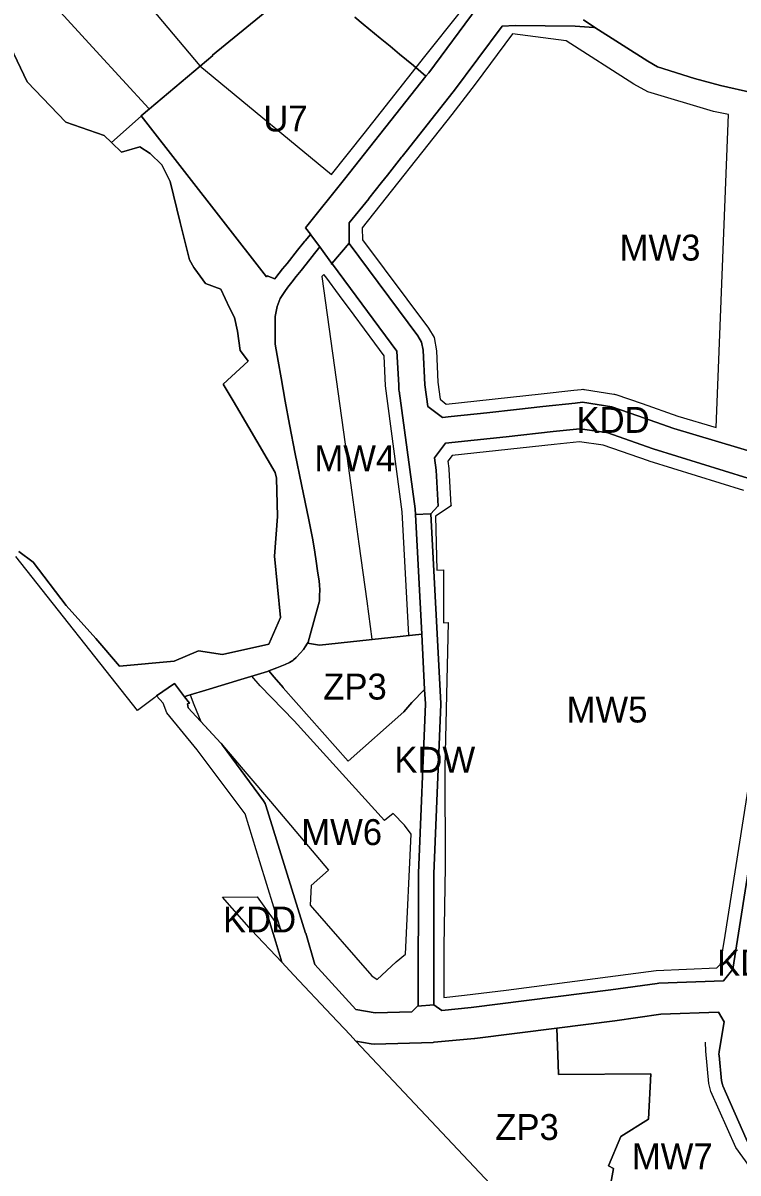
# Model space of a CAD drawing. Extents: x 7425930 to 7427318, y 5544765 to 5546387.
# Drawn here: x 7426422.5 to 7426698.5, y 5545008.8 to 5545452.3 of the extents above; entities that cross this region are included whole.
import ezdxf

# ---------------------------------------------------------------- set-up
doc = ezdxf.new("R2010")
doc.units = 0
for name, color, linetype in [('linie_rozgraniczajace', 7, 'Continuous'), ('linie_zabudowy_nieprzekraczalne', 7, 'Continuous'), ('linie_zabudowy_obowiazujace', 7, 'Continuous'), ('oznaczenia_przeznaczen', 7, 'Continuous')]:
    doc.layers.add(name, color=color, linetype=linetype)

msp = doc.modelspace()

# ---------------------------------------------------------------- linework, layer by layer
at = {"layer": 'linie_rozgraniczajace'}
for points in [[(7426531.91, 5545469.68), (7426495.6, 5545439.93), (7426495.7, 5545439.81), (7426471.26, 5545419.17), (7426471.04, 5545419.4), (7426450.76, 5545441.52), (7426428.57, 5545465.75)], [(7426550.61, 5545454.54), (7426553.81, 5545451.91), (7426560.37, 5545446.51), (7426564.14, 5545443.41), (7426567.86, 5545440.35), (7426573.15, 5545435.88), (7426576.02, 5545433.47), (7426578.02, 5545431.79), (7426546.56, 5545392.08), (7426531.53, 5545373.36), (7426533.4, 5545370.84), (7426533.41, 5545370.82), (7426531.38, 5545368.35), (7426531.11, 5545368.02), (7426528.49, 5545364.77), (7426524.39, 5545359.61), (7426522.68, 5545357.53), (7426520.11, 5545354.23), (7426519.67, 5545353.61), (7426516.75, 5545354.84), (7426516.51, 5545354.48), (7426468.15, 5545416.47), (7426468.12, 5545416.51), (7426471.26, 5545419.17), (7426495.7, 5545439.81), (7426495.6, 5545439.93), (7426531.91, 5545469.68)], [(7426428.57, 5545465.75), (7426450.76, 5545441.52), (7426471.04, 5545419.4), (7426471.26, 5545419.17), (7426468.12, 5545416.51), (7426468.15, 5545416.47), (7426468.08, 5545416.46), (7426456.63, 5545406.26), (7426453.83, 5545408.94), (7426439.06, 5545414.08), (7426424.06, 5545429.61), (7426417.71, 5545443.09), (7426415.29, 5545454.53)], [(7426638.81, 5545453.6), (7426643.25, 5545450.62), (7426642.75, 5545450.65), (7426635.57, 5545451.11), (7426612.46, 5545451.38), (7426607.43, 5545451.14), (7426588.68, 5545425.93), (7426588.59, 5545425.82), (7426588.57, 5545425.79), (7426570.37, 5545402.81), (7426568.81, 5545400.84), (7426568.64, 5545400.63), (7426568.64, 5545400.65), (7426563.18, 5545393.71), (7426563.18, 5545393.73), (7426563.14, 5545393.69), (7426560.9, 5545390.86), (7426555.95, 5545384.61), (7426555.94, 5545384.6), (7426555.93, 5545384.58), (7426548.43, 5545375.24), (7426548.35, 5545367.45), (7426541.73, 5545359.6), (7426539, 5545363.28), (7426537.02, 5545365.95), (7426533.41, 5545370.82), (7426533.4, 5545370.84), (7426531.53, 5545373.36), (7426546.56, 5545392.08), (7426578.02, 5545431.79), (7426579.11, 5545433.17), (7426597.8, 5545458.3)], [(7426597.8, 5545458.3), (7426579.11, 5545433.17), (7426578.02, 5545431.79), (7426576.02, 5545433.47), (7426573.15, 5545435.88), (7426567.86, 5545440.35), (7426564.14, 5545443.41), (7426560.37, 5545446.51), (7426553.81, 5545451.91), (7426550.61, 5545454.54)], [(7426704.2, 5545425.45), (7426691.68, 5545428.29), (7426681.66, 5545430.95), (7426667.42, 5545435.49), (7426663.59, 5545437.66), (7426643.25, 5545450.62), (7426638.81, 5545453.6)], [(7426706.86, 5545286), (7426673.73, 5545295.93), (7426659.83, 5545300.81), (7426649.7, 5545304.3), (7426638.44, 5545306.06), (7426635.65, 5545305.77), (7426623.07, 5545304.4), (7426612.94, 5545303.29), (7426601.56, 5545302.04), (7426587.78, 5545300.54), (7426584.4, 5545300.17), (7426578.71, 5545304.48), (7426577.62, 5545312.79), (7426576.94, 5545326.13), (7426576.28, 5545329.28), (7426574.86, 5545331.74), (7426548.35, 5545367.35), (7426548.35, 5545367.45), (7426548.43, 5545375.24), (7426555.93, 5545384.58), (7426555.94, 5545384.6), (7426555.95, 5545384.61), (7426560.9, 5545390.86), (7426563.14, 5545393.69), (7426563.18, 5545393.73), (7426563.18, 5545393.71), (7426568.64, 5545400.65), (7426568.64, 5545400.63), (7426568.81, 5545400.84), (7426570.37, 5545402.81), (7426588.57, 5545425.79), (7426588.59, 5545425.82), (7426588.68, 5545425.93), (7426607.43, 5545451.14), (7426612.46, 5545451.38), (7426635.57, 5545451.11), (7426642.75, 5545450.65), (7426643.25, 5545450.62), (7426663.59, 5545437.66), (7426667.42, 5545435.49), (7426681.66, 5545430.95), (7426691.68, 5545428.29), (7426704.2, 5545425.45)], [(7426417.71, 5545443.09), (7426424.06, 5545429.61), (7426439.06, 5545414.08), (7426453.83, 5545408.94), (7426456.63, 5545406.26), (7426456.79, 5545406.11), (7426460.52, 5545402.53), (7426467.63, 5545404.58), (7426471.52, 5545401.96), (7426476.11, 5545397.61), (7426479.27, 5545391.18), (7426483.12, 5545375.39), (7426486.73, 5545361.04), (7426488.37, 5545358.08), (7426488.76, 5545357.54), (7426492.91, 5545351.83), (7426498.79, 5545349.67), (7426502.24, 5545342.5), (7426504.15, 5545338.8), (7426505.25, 5545333.42), (7426506.31, 5545326.02), (7426507.94, 5545323.89), (7426509.38, 5545321.86), (7426499.78, 5545313.02), (7426503.55, 5545306.64), (7426509.66, 5545296.31), (7426519.88, 5545278.94), (7426520.33, 5545276.73), (7426520.7, 5545261.99)], [(7426479.27, 5545391.18), (7426476.11, 5545397.61), (7426471.52, 5545401.96), (7426467.63, 5545404.58), (7426460.52, 5545402.53), (7426456.79, 5545406.11), (7426456.63, 5545406.26), (7426468.08, 5545416.46), (7426468.15, 5545416.47), (7426516.51, 5545354.48), (7426516.75, 5545354.84), (7426519.67, 5545353.61), (7426520.11, 5545354.23), (7426522.68, 5545357.53), (7426524.39, 5545359.61), (7426528.49, 5545364.77), (7426531.11, 5545368.02), (7426531.38, 5545368.35), (7426533.41, 5545370.82), (7426537.02, 5545365.95), (7426535.05, 5545363.42), (7426533.24, 5545361.1), (7426529.88, 5545356.84), (7426527.98, 5545354.52), (7426526.25, 5545352.4), (7426524.76, 5545350.44), (7426523.6, 5545348.78), (7426522.55, 5545347.3), (7426521.76, 5545346.13), (7426520.63, 5545343.03), (7426519.82, 5545339.09), (7426519.81, 5545334.06), (7426519.88, 5545328.45), (7426521.02, 5545321.87), (7426522.12, 5545315.47), (7426523.66, 5545306.53), (7426525.34, 5545297.48), (7426527.58, 5545286.21), (7426530, 5545274.35), (7426532.79, 5545260.69), (7426534.19, 5545253.64), (7426534.92, 5545249.86), (7426535.54, 5545245.63), (7426536.33, 5545240.18), (7426536.76, 5545237.25), (7426536.93, 5545235.52), (7426537.08, 5545233.68), (7426536.97, 5545231.36), (7426536.91, 5545229.43), (7426536.83, 5545228.94), (7426536.22, 5545226.68), (7426533.74, 5545217.72), (7426532.93, 5545214.93), (7426532.52, 5545213.56), (7426532.26, 5545213.13), (7426531.43, 5545211.72), (7426530.71, 5545210.74), (7426529.61, 5545209.41), (7426527.88, 5545207.68), (7426526.93, 5545206.77), (7426526.62, 5545206.5), (7426525.38, 5545205.72), (7426523.63, 5545204.98), (7426520.4, 5545203.65), (7426517.33, 5545202.45), (7426516.86, 5545202.27), (7426506.56, 5545199.12), (7426494.29, 5545195.39), (7426485.75, 5545192.8), (7426484.76, 5545192.48), (7426480.9, 5545197.54), (7426474.06, 5545192.78), (7426473.36, 5545192.25), (7426466.72, 5545187.23), (7426419.78, 5545246.57)], [(7426420.88, 5545248.48), (7426426.47, 5545244.42), (7426439.13, 5545227.66), (7426450.61, 5545214.89), (7426459.74, 5545204.29), (7426480.85, 5545206.15), (7426490.27, 5545210.19), (7426499.47, 5545208.74), (7426517.34, 5545212.74), (7426521.84, 5545223.01), (7426519.61, 5545246.75), (7426520.7, 5545261.99), (7426520.33, 5545276.73), (7426519.88, 5545278.94), (7426509.66, 5545296.31), (7426503.55, 5545306.64), (7426499.78, 5545313.02), (7426509.38, 5545321.86), (7426507.94, 5545323.89), (7426506.31, 5545326.02), (7426505.25, 5545333.42), (7426504.15, 5545338.8), (7426502.24, 5545342.5), (7426498.79, 5545349.67), (7426492.91, 5545351.83), (7426488.76, 5545357.54), (7426488.37, 5545358.08), (7426486.73, 5545361.04), (7426483.12, 5545375.39), (7426479.27, 5545391.18)], [(7426702.26, 5545276.73), (7426665.69, 5545288.13), (7426647.84, 5545294.37), (7426647.67, 5545294.43), (7426637.42, 5545295.85), (7426627.12, 5545294.78), (7426608.93, 5545292.79), (7426596.61, 5545291.44), (7426585.6, 5545290.24), (7426581.33, 5545284.68), (7426581.96, 5545279.87), (7426582.79, 5545266.05), (7426582.58, 5545266.05), (7426579.96, 5545263.01), (7426579.83, 5545263.03), (7426573.94, 5545262.79), (7426573.83, 5545265.01), (7426567.62, 5545310.45), (7426567.6, 5545310.68), (7426567.6, 5545310.69), (7426567.5, 5545312.59), (7426566.8, 5545325.78), (7426541.92, 5545359.34), (7426541.58, 5545359.36), (7426541.62, 5545359.46), (7426541.73, 5545359.6), (7426548.35, 5545367.45), (7426548.35, 5545367.35), (7426574.86, 5545331.74), (7426576.28, 5545329.28), (7426576.94, 5545326.13), (7426577.62, 5545312.79), (7426578.71, 5545304.48), (7426584.4, 5545300.17), (7426587.78, 5545300.54), (7426601.56, 5545302.04), (7426612.94, 5545303.29), (7426623.07, 5545304.4), (7426635.65, 5545305.77), (7426638.44, 5545306.06), (7426649.7, 5545304.3), (7426659.83, 5545300.81), (7426673.73, 5545295.93), (7426706.86, 5545286)], [(7426709.77, 5545171.52), (7426696.47, 5545087.37), (7426692.88, 5545082.9), (7426667.9, 5545082), (7426667.89, 5545081.99), (7426667.88, 5545082), (7426667.29, 5545081.94), (7426649.36, 5545079.43), (7426595.49, 5545072.62), (7426584.11, 5545071.53), (7426581.12, 5545073.63), (7426581.04, 5545073.68), (7426581, 5545076.17), (7426581.1, 5545124.22), (7426583.8, 5545189.61), (7426583.8, 5545189.85), (7426583.8, 5545189.87), (7426583.8, 5545189.89), (7426579.94, 5545262.99), (7426579.96, 5545263.01), (7426582.58, 5545266.05), (7426582.79, 5545266.05), (7426581.96, 5545279.87), (7426581.33, 5545284.68), (7426585.6, 5545290.24), (7426596.61, 5545291.44), (7426608.93, 5545292.79), (7426627.12, 5545294.78), (7426637.42, 5545295.85), (7426647.67, 5545294.43), (7426647.84, 5545294.37), (7426665.69, 5545288.13), (7426702.26, 5545276.73)], [(7426520.7, 5545261.99), (7426519.61, 5545246.75), (7426521.84, 5545223.01), (7426517.34, 5545212.74), (7426499.47, 5545208.74), (7426490.27, 5545210.19), (7426480.85, 5545206.15), (7426459.74, 5545204.29), (7426450.61, 5545214.89), (7426439.13, 5545227.66), (7426426.47, 5545244.42), (7426420.88, 5545248.48)], [(7426474.06, 5545192.78), (7426480.9, 5545197.54), (7426484.76, 5545192.48), (7426486.7, 5545189.95), (7426485.94, 5545189.72), (7426486.2, 5545188.19), (7426498.81, 5545174.63), (7426499.09, 5545174.33), (7426499.2, 5545174.17), (7426499.53, 5545173.81), (7426515.36, 5545152.34), (7426515.98, 5545151.3), (7426516.26, 5545150.56), (7426531.56, 5545101.33), (7426531.57, 5545101.3), (7426531.59, 5545101.24), (7426535.12, 5545089.17), (7426550.97, 5545071.89), (7426558.37, 5545070.53), (7426572.56, 5545070.94), (7426574.73, 5545073.12), (7426581.12, 5545073.63), (7426584.11, 5545071.53), (7426595.49, 5545072.62), (7426649.36, 5545079.43), (7426667.29, 5545081.94), (7426667.88, 5545082), (7426667.89, 5545081.99), (7426667.9, 5545082), (7426692.88, 5545082.9), (7426696.47, 5545087.37), (7426709.77, 5545171.52)], [(7426692.06, 5545044.32), (7426691.13, 5545054.08), (7426691.15, 5545054.23), (7426691.11, 5545054.4), (7426691.19, 5545055.65), (7426693.14, 5545067.12), (7426690.97, 5545070.83), (7426668.65, 5545070.02), (7426650.98, 5545067.54), (7426650.92, 5545067.54), (7426650.9, 5545067.53), (7426628.57, 5545064.71), (7426596.9, 5545060.71), (7426596.75, 5545060.69), (7426596.72, 5545060.69), (7426581.23, 5545059.2), (7426581.04, 5545059.22), (7426580.83, 5545059.17), (7426558.08, 5545058.51), (7426558, 5545058.53), (7426556.82, 5545058.61), (7426550.99, 5545059.69), (7426548.79, 5545062.03), (7426541.58, 5545069.68), (7426527.02, 5545085.15), (7426522.35, 5545090.1), (7426520.09, 5545097.82), (7426516.07, 5545110.75), (7426521.96, 5545102.53), (7426513.88, 5545128.83), (7426508.23, 5545147.27), (7426489.66, 5545172.05), (7426478.02, 5545186.31), (7426476.64, 5545189.98), (7426474.06, 5545192.78)], [(7426647.24, 5544992.98), (7426650.37, 5545010.58), (7426648.48, 5545011.56), (7426653.18, 5545022.87), (7426663.9, 5545029.53), (7426664.78, 5545047.04), (7426629.17, 5545046.79), (7426629.01, 5545050.75), (7426628.57, 5545064.71), (7426650.9, 5545067.53), (7426650.92, 5545067.54), (7426650.98, 5545067.54), (7426668.65, 5545070.02), (7426690.97, 5545070.83), (7426693.14, 5545067.12), (7426691.19, 5545055.65), (7426691.11, 5545054.4), (7426691.15, 5545054.23), (7426691.13, 5545054.08), (7426692.06, 5545044.32), (7426692.43, 5545042.95), (7426692.54, 5545042.47), (7426701.58, 5545021.92)], [(7426715.65, 5545001.38), (7426702.14, 5545020.92), (7426701.63, 5545021.81), (7426701.61, 5545021.87), (7426701.58, 5545021.92), (7426692.54, 5545042.47), (7426692.43, 5545042.95), (7426692.06, 5545044.32)]]:
    msp.add_lwpolyline(points, dxfattribs=at)
for points in [[(7426519.88, 5545328.45), (7426519.81, 5545334.06), (7426519.82, 5545339.09), (7426520.63, 5545343.03), (7426521.76, 5545346.13), (7426522.55, 5545347.3), (7426523.6, 5545348.78), (7426524.76, 5545350.44), (7426526.25, 5545352.4), (7426527.98, 5545354.52), (7426529.88, 5545356.84), (7426533.24, 5545361.1), (7426535.05, 5545363.42), (7426537.02, 5545365.95), (7426539, 5545363.28), (7426541.73, 5545359.6), (7426541.62, 5545359.46), (7426541.58, 5545359.36), (7426541.92, 5545359.34), (7426566.8, 5545325.78), (7426567.5, 5545312.59), (7426567.6, 5545310.69), (7426567.6, 5545310.68), (7426567.62, 5545310.45), (7426573.83, 5545265.01), (7426573.94, 5545262.79), (7426576.39, 5545216.57), (7426536.9, 5545212.38), (7426535.39, 5545212.62), (7426532.26, 5545213.13), (7426532.52, 5545213.56), (7426532.93, 5545214.93), (7426533.74, 5545217.72), (7426536.22, 5545226.68), (7426536.83, 5545228.94), (7426536.91, 5545229.43), (7426536.97, 5545231.36), (7426537.08, 5545233.68), (7426536.93, 5545235.52), (7426536.76, 5545237.25), (7426536.33, 5545240.18), (7426535.54, 5545245.63), (7426534.92, 5545249.86), (7426534.19, 5545253.64), (7426532.79, 5545260.69), (7426530, 5545274.35), (7426527.58, 5545286.21), (7426525.34, 5545297.48), (7426523.66, 5545306.53), (7426522.12, 5545315.47), (7426521.02, 5545321.87)], [(7426574.73, 5545073.12), (7426575.05, 5545073.44), (7426575, 5545076.11), (7426575.01, 5545076.14), (7426575, 5545076.16), (7426575.1, 5545124.29), (7426575.1, 5545124.3), (7426575.11, 5545124.41), (7426577.8, 5545189.71), (7426577.51, 5545195.34), (7426576.39, 5545216.57), (7426573.94, 5545262.79), (7426579.83, 5545263.03), (7426579.96, 5545263.01), (7426579.94, 5545262.99), (7426583.8, 5545189.89), (7426583.8, 5545189.87), (7426583.8, 5545189.85), (7426583.8, 5545189.61), (7426581.1, 5545124.22), (7426581, 5545076.17), (7426581.04, 5545073.68), (7426581.12, 5545073.63)], [(7426517.33, 5545202.45), (7426520.4, 5545203.65), (7426523.63, 5545204.98), (7426525.38, 5545205.72), (7426526.62, 5545206.5), (7426526.93, 5545206.77), (7426527.88, 5545207.68), (7426529.61, 5545209.41), (7426530.71, 5545210.74), (7426531.43, 5545211.72), (7426532.26, 5545213.13), (7426535.39, 5545212.62), (7426536.9, 5545212.38), (7426576.39, 5545216.57), (7426577.51, 5545195.34), (7426572.62, 5545190.26), (7426569.46, 5545186.69), (7426547.99, 5545167.68), (7426522.96, 5545195.95), (7426522.95, 5545196.02), (7426519.48, 5545199.99)], [(7426484.76, 5545192.48), (7426485.75, 5545192.8), (7426494.29, 5545195.39), (7426506.56, 5545199.12), (7426516.86, 5545202.27), (7426517.33, 5545202.45), (7426519.48, 5545199.99), (7426522.95, 5545196.02), (7426522.96, 5545195.95), (7426547.99, 5545167.68), (7426569.46, 5545186.69), (7426572.62, 5545190.26), (7426577.51, 5545195.34), (7426577.8, 5545189.71), (7426575.11, 5545124.41), (7426575.1, 5545124.3), (7426575.1, 5545124.29), (7426575, 5545076.16), (7426575.01, 5545076.14), (7426575, 5545076.11), (7426575.05, 5545073.44), (7426574.73, 5545073.12), (7426572.56, 5545070.94), (7426558.37, 5545070.53), (7426550.97, 5545071.89), (7426535.12, 5545089.17), (7426531.59, 5545101.24), (7426531.57, 5545101.3), (7426531.56, 5545101.33), (7426516.26, 5545150.56), (7426515.98, 5545151.3), (7426515.36, 5545152.34), (7426499.53, 5545173.81), (7426499.2, 5545174.17), (7426499.09, 5545174.33), (7426498.81, 5545174.63), (7426486.2, 5545188.19), (7426485.94, 5545189.72), (7426486.7, 5545189.95)], [(7426499.5, 5545115.2), (7426512.84, 5545115.26), (7426516.07, 5545110.75), (7426520.09, 5545097.82), (7426522.35, 5545090.1), (7426510.68, 5545102.49)], [(7426550.99, 5545059.69), (7426556.82, 5545058.61), (7426558, 5545058.53), (7426558.08, 5545058.51), (7426580.83, 5545059.17), (7426581.04, 5545059.22), (7426581.23, 5545059.2), (7426596.72, 5545060.69), (7426596.75, 5545060.69), (7426596.9, 5545060.71), (7426628.57, 5545064.71), (7426629.01, 5545050.75), (7426629.17, 5545046.79), (7426664.78, 5545047.04), (7426663.9, 5545029.53), (7426653.18, 5545022.87), (7426648.48, 5545011.56), (7426650.37, 5545010.58), (7426647.24, 5544992.98), (7426646.45, 5544986.59), (7426644.66, 5544973.48), (7426637.91, 5544966.51), (7426619.41, 5544987.05)]]:
    msp.add_lwpolyline(points, close=True, dxfattribs=at)
at = {"layer": 'linie_zabudowy_nieprzekraczalne'}
for points in [[(7426453.7, 5545479.94), (7426490.8, 5545435.83), (7426541.62, 5545393.94), (7426554.17, 5545409.67), (7426577.53, 5545439.41), (7426591.38, 5545456.69), (7426593.37, 5545460.97)], [(7426611.39, 5545448.12), (7426597.03, 5545428.68), (7426588.03, 5545417), (7426553.38, 5545373.3), (7426553.57, 5545368.68), (7426579.05, 5545334.63), (7426581.18, 5545331.01), (7426582.11, 5545325.95), (7426582.61, 5545313.79), (7426583.48, 5545307.21), (7426585.83, 5545305.35), (7426622.53, 5545309.37), (7426635.1, 5545310.74), (7426635.12, 5545310.74), (7426635.14, 5545310.74), (7426637.93, 5545311.03), (7426638.57, 5545311.06), (7426638.89, 5545311.04), (7426639.21, 5545311), (7426650.47, 5545309.24), (7426650.48, 5545309.24), (7426650.8, 5545309.18), (7426651.12, 5545309.1), (7426651.33, 5545309.03), (7426661.46, 5545305.54), (7426661.49, 5545305.53), (7426675.28, 5545300.69), (7426689.97, 5545296.33), (7426694.76, 5545417.03)], [(7426571.41, 5545216.22), (7426568.88, 5545263.85), (7426562.41, 5545312.44), (7426561.88, 5545324.01), (7426558.25, 5545328.91), (7426550.32, 5545339.61), (7426544.68, 5545347.22), (7426539.32, 5545354.45), (7426538.64, 5545355.37), (7426537.79, 5545354.58), (7426547.44, 5545285.22), (7426549.39, 5545271.2), (7426552.1, 5545251.48), (7426555.24, 5545229.29), (7426557.16, 5545214.66)], [(7426700.67, 5545271.98), (7426664.11, 5545283.38), (7426663.95, 5545283.44), (7426646.4, 5545289.57), (7426637.24, 5545290.83), (7426627.56, 5545289.83), (7426588.17, 5545285.52), (7426586.46, 5545283.3), (7426586.83, 5545280.55), (7426586.84, 5545280.42), (7426586.86, 5545280.19), (7426587.68, 5545266.37), (7426587.68, 5545266.33), (7426587.69, 5545266.28), (7426587.69, 5545266.11), (7426581.73, 5545262.15), (7426582.25, 5545241.27), (7426584.78, 5545241.38), (7426584.83, 5545221.03), (7426586.54, 5545221.1), (7426585.3, 5545165.31), (7426585.45, 5545126.93), (7426584.98, 5545096.11), (7426584.98, 5545076.48), (7426592.86, 5545077.37), (7426608.93, 5545079.34), (7426666.81, 5545086.92), (7426690.33, 5545087.88), (7426691.73, 5545089.39), (7426693.47, 5545100.38), (7426704.48, 5545170.01)], [(7426486.97, 5545193.17), (7426488.38, 5545189.54), (7426491.12, 5545182.98), (7426498.81, 5545174.63), (7426508.86, 5545162.71), (7426518.03, 5545152.04), (7426540.41, 5545125.66), (7426533.74, 5545119.64), (7426533.38, 5545112.14), (7426557.13, 5545084.84), (7426559.17, 5545083.47), (7426566.57, 5545090.25), (7426570.16, 5545093.18), (7426572.34, 5545139.45), (7426569.71, 5545143.01), (7426565.4, 5545147.46), (7426561.99, 5545144.73), (7426527.2, 5545183.18), (7426514.04, 5545196.74), (7426510.82, 5545200.42)], [(7426858.11, 5544805.51), (7426838.33, 5544831.26), (7426800.21, 5544878.94), (7426791.21, 5544889.94), (7426760.21, 5544929.31), (7426764.88, 5544933.06), (7426730.1, 5544977.78), (7426723.05, 5544985.09), (7426715.52, 5544993.89), (7426697.67, 5545018.58), (7426687.92, 5545040.29), (7426687.14, 5545043.3), (7426686.1, 5545055.84), (7426685.97, 5545059.25)]]:
    msp.add_lwpolyline(points, dxfattribs=at)
at = {"layer": 'linie_zabudowy_obowiazujace'}
msp.add_lwpolyline([(7426694.76, 5545417.03), (7426689.04, 5545418.23), (7426663.71, 5545425.8), (7426658.29, 5545428.76), (7426632.19, 5545445.44), (7426611.39, 5545448.12)], dxfattribs=at)

# ---------------------------------------------------------------- texts
at = {"layer": 'oznaczenia_przeznaczen'}
for s, p in [('U7', (7426515.24, 5545410.51)), ('MW3', (7426652.75, 5545360.71)), ('KDD', (7426636.13, 5545294.26)), ('MW4', (7426534.96, 5545279.45)), ('ZP3', (7426538.36, 5545191.4)), ('MW5', (7426632.3, 5545182.55)), ('KDW', (7426565.82, 5545163.18)), ('MW6', (7426529.88, 5545135.27)), ('KDD', (7426499.69, 5545101.56)), ('KDL', (7426690.35, 5545084.97)), ('ZP3', (7426604.75, 5545021.53)), ('MW7', (7426657.48, 5545010.22))]:
    msp.add_text(s, height=10, dxfattribs=at).set_placement(p)

doc.saveas('drawing.dxf')
